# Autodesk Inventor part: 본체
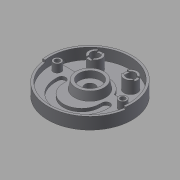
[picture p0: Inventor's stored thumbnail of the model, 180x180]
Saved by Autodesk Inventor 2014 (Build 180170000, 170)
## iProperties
Created: 2015-06
Part Number: 본체
Material: Generic
Document SubType Name: Modeling
Designer: MYHOME
Density: 1 g/cm^3
Appearance: Default
Author: MYHOME
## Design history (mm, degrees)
sketch "스케치16"
  geometry: C1 r 95 at (0, 0); 1 further point
  constraints: 1 centre point, 1 coincident
  dimensions: "d45" = 95 radius of C1
extrude "돌출11" new body sketch "스케치16" distance "d46" = 32; taper "d47" = 0 deg
sketch "스케치18"
  geometry: C1 r 95 at (0, 0) reference; C2 r 26 at (0, 0)
  constraints: 1 centre point, 1 coincident
  dimensions: "d51" = 26 radius of C2
extrude "돌출13" join sketch "스케치18" distance "d52" = 12; taper "d53" = -15 deg
sketch "스케치24"
  geometry: C1 r 95 at (0, 0) reference; C2 r 90 at (0, 0)
  constraints: 1 centre point, 1 coincident
  dimensions: "d84" = 90 radius of C2
extrude "돌출17" cut sketch "스케치24" distance "d85" = 25; taper "d86" = 0 deg
sketch "스케치25"
  geometry: L1 (-88.566, 16)-(88.566, 16); C1 r 42 at (0, 0); A1 r 90 centre (0, 0) between (-88.566, 16) and (88.566, 16) reference
  constraints: 2 end point, 2 point on circle, 1 centre point, 1 coincident, 1 horizontal
  dimensions: "d87" = 42 radius of C1; "d88" = 16 distance from line of L1 C1.centre
extrude "돌출18" join sketch "스케치25" distance "d89" = 7; taper "d90" = 0 deg
sketch "스케치26"
  geometry: L1 (88.566, 16)-(38.833, 16) reference; L2 (50, -19)-(50, -14); L3 (41, -19)-(41, -14); L4 (59, -19)-(59, -14); L5 (-50, -19)-(-50, -14); L6 (-59, -19)-(-59, -14); L7 (-41, -19)-(-41, -14); A1 r 90 centre (0, 0) between (-88.566, 16) and (88.566, 16) reference; A2 r 50 centre (0, -19) between (-50, -19) and (50, -19); A3 r 59 centre (0, -19) between (-59, -19) and (59, -19); A4 r 41 centre (0, -19) between (-41, -19) and (41, -19); A5 r 9 centre (-50, -19) between (-41, -19) and (-59, -19); A6 r 9 centre (50, -19) between (59, -19) and (41, -19); A7 r 9 centre (50, -14) between (41, -14) and (59, -14); A8 r 9 centre (-50, -14) between (-59, -14) and (-41, -14)
  constraints: 15 point on circle, 12 end point, 11 tangent, 7 centre point, 2 coincident, 2 horizontal alignment, 2 parallel, 1 perpendicular, 1 vertical alignment
  dimensions: "d91" = 19 distance of A2.centre A1.centre; "d92" = 41 radius of A4; "d93" = 18 radial gap between concentric circles of A3 A4; "d94" = 5 distance of L2.start L2.end; "d95" = 9 radius of A7; "d96" = 5 distance of L5.start L5.end; "d97" = 9 radius of A8
extrude "돌출19" cut sketch "스케치26" distance "d98" = 7; taper "d99" = 0 deg
fillet "모깎기3" dims "d100" = 10
sketch "스케치27"
  geometry: C1 r 35 at (0, 0); A1 r 42 centre (0, 0) between (38.833, 16) and (-38.833, 16) reference
  constraints: 1 centre point, 1 coincident
  dimensions: "d101" = 35 radius of C1
extrude "돌출20" join sketch "스케치27" distance "d102" = 18; taper "d103" = -10 deg
sketch "스케치28"
  geometry: C1 r 31.826 at (0, 0) reference; C2 r 25 at (0, 0)
  constraints: 1 centre point, 1 coincident
  dimensions: "d104" = 25 radius of C2
extrude "돌출21" cut sketch "스케치28" distance "d105" = 15; taper "d106" = 0 deg
sketch "스케치29"
  geometry: C1 r 25 at (0, 0) reference; C2 r 11.5 at (0, 0)
  constraints: 1 centre point, 1 coincident
  dimensions: "d107" = 11.5 radius of C2
extrude "돌출22" cut sketch "스케치29" stored distance "d108" = 15; taper "d109" = 0 deg
sketch "스케치31"
  geometry: C1 r 15 at (-40, 52); C2 r 15 at (40, 52); A1 r 90 centre (0, 0) between (85.114, 29.25) and (-85.114, 29.25) reference
  constraints: 2 centre point
  dimensions: "d111" = 15 radius of C1; "d112" = 15 radius of C2; "d113" = 52 vertical distance of C2.centre A1.centre; "d114" = 52 vertical distance of C1.centre A1.centre; "d115" = 40 horizontal distance of A1.centre C1.centre; "d116" = 40 horizontal distance of C2.centre A1.centre
extrude "돌출23" join sketch "스케치31" distance "d117" = 25; taper "d118" = 0 deg
sketch "스케치32"
  geometry: C1 r 15 at (0, 0) reference; C2 r 15 at (80, 0) reference; C3 r 10 at (0, 0); C4 r 10 at (80, 0); 1 further point
  constraints: 2 centre point, 2 coincident
  dimensions: "d119" = 10 radius of C3; "d120" = 10 radius of C4
extrude "돌출24" cut sketch "스케치32" stored distance "d121" = 25; taper "d122" = 0 deg
sketch "스케치33"
  geometry: L1 (-6, -13.748)-(-6, -8); L2 (-6, 8)-(-6, 13.748); L3 (6, 13.748)-(6, 8); L4 (6, -8)-(6, -13.748); C1 r 10 at (0, 0); C2 r 15 at (0, 0); A1 r 10 centre (0, 0) between (-6, -8) and (-6, 8) reference; A2 r 15 centre (0, 0) between (-6, -13.748) and (-6, 13.748) reference; 1 further point
  constraints: 8 end point, 8 point on circle, 4 parallel, 3 coincident, 2 centre point, 2 concentric, 2 vertical
  dimensions: "d125" = 6 distance from line of L2 A1.centre; "d126" = 6 distance from line of L3 A1.centre; "d127" = 6 distance from line of L1 A1.centre; "d128" = 6 distance from line of L4 A1.centre
extrude "돌출25" join sketch "스케치33" distance "d129" = 3; taper "d130" = 0 deg
sketch "스케치34"
  geometry: L1 (-13.733, -6.033)-(-7.986, -6.019); L2 (8.014, -5.981)-(13.762, -5.967); L3 (-13.749, 5.998)-(-8.001, 5.999); L4 (7.999, 6.001)-(13.747, 6.002); C1 r 10 at (0, 0) reference; A1 r 15 centre (0, 0) between (-13.749, 5.998) and (13.747, 6.002) reference; A2 r 15 centre (0, 0) between (-13.749, 5.998) and (13.747, 6.002); A3 r 10 centre (0, 0) between (-7.986, -6.019) and (8.014, -5.981); 1 further point
  constraints: 12 point on circle, 8 end point, 2 centre point, 2 coincident, 2 concentric
  dimensions: "d133" = 6 distance from line of L3 C1.centre; "d134" = 6 distance from line of L1 C1.centre; "d135" = 6 distance from line of L4 C1.centre; "d136" = 6 distance from line of L2 C1.centre; "d137" = 5.98106 vertical distance of L2.start C1.centre; "d138" = 7.98578 horizontal distance of L1.end C1.centre; "d139" = 5.99882 vertical distance of L3.end C1.centre; "d140" = 7.99911 horizontal distance of L4.start C1.centre
extrude "돌출26" join sketch "스케치34" distance "d141" = 3; taper "d142" = 0 deg
sketch "스케치38"
  geometry: C1 r 10 at (40, 52) reference; C2 r 10 at (-40, 52) reference; C3 r 26 at (0, 0) reference; C4 r 9 at (-74, 0); C5 r 9 at (74, 0)
  constraints: 2 centre point
  dimensions: "d146" = 9 radius of C4; "d147" = 9 radius of C5; "d148" = 52 vertical distance of C4.centre C2.centre; "d149" = 52 vertical distance of C5.centre C1.centre; "d150" = 74 distance of C3.centre C4.centre; "d151" = 74 distance of C5.centre C3.centre
extrude "돌출27" cut sketch "스케치38" distance "d152" = 11; taper "d153" = 0 deg
sketch "스케치40"
  geometry: C1 r 35 at (0, 0) reference; C2 r 9 at (-74, 0); C3 r 9 at (74, 0); A1 r 10 centre (-40, 52) between (-46, 60) and (-46, 44) reference; A2 r 10 centre (40, 52) between (31.999, 57.999) and (32.014, 45.981) reference
  constraints: 2 centre point
  dimensions: "d156" = 9 radius of C2; "d157" = 9 radius of C3; "d158" = 74 distance of C1.centre C2.centre; "d159" = 74 distance of C3.centre C1.centre; "d160" = 52 vertical distance of A1.centre C2.centre; "d161" = 52 vertical distance of A2.centre C3.centre
extrude "돌출28" join sketch "스케치40" distance "d162" = 18; taper "d163" = 0 deg
sketch "스케치43"
  geometry: C1 r 9 at (0, 0) reference; C2 r 5.5 at (0, 0); C3 r 5.5 at (148, 0); C4 r 10 at (114, 52) reference; 1 further point
  constraints: 2 centre point, 1 coincident
  dimensions: "d164" = 5.5 radius of C2; "d165" = 5.5 radius of C3; "d166" = 74 distance of C3.centre point (74, 0); "d167" = 52 vertical distance of C4.centre C3.centre
extrude "돌출29" cut sketch "스케치43" stored distance "d168" = 18; taper "d169" = 0 deg
sketch "스케치44"
  geometry: L1 (-95, 0)-(0, 0); L2 (0, 0)-(-89.124, -12.526); L3 (0, 0)-(95, 0); L4 (0, 0)-(89.124, -12.526); L5 (-89.124, -12.526)-(-94.075, -13.221); L6 (89.124, -12.526)-(94.075, -13.221); A1 r 90 centre (0, 0) between (-89.024, -13.221) and (89.024, -13.221) reference; A2 r 95 centre (0, 0) between (-95, 0) and (-94.075, -13.221) reference
  constraints: 12 end point, 8 point on circle, 1 collinear, 1 horizontal
  dimensions: "d170" = 8 deg angle of L1 L2; "d172" = 8 deg angle of L3 L4; "d173" = 8 deg angle of L3 L6; "d174" = 8 deg angle of L1 L5
extrude "돌출30" cut sketch "스케치44" distance "d175" = 5; taper "d176" = 0 deg
sketch "스케치46"
  geometry: C1 r 95 at (0, 0) reference; C2 r 68 at (0, 0)
  constraints: 1 centre point, 1 coincident, 1 other
  dimensions: "d178" = 68 radius of C2
feature "엠보싱1" sketch "스케치46" dims "d88" = 16, "d180" = 0.5, "d181" = 0
node "솔리드2"
other parameters: "d58" = 16, "d65" = 52, "d66" = 16, "d71" = 52, "d131" = 6, "d132" = 6
